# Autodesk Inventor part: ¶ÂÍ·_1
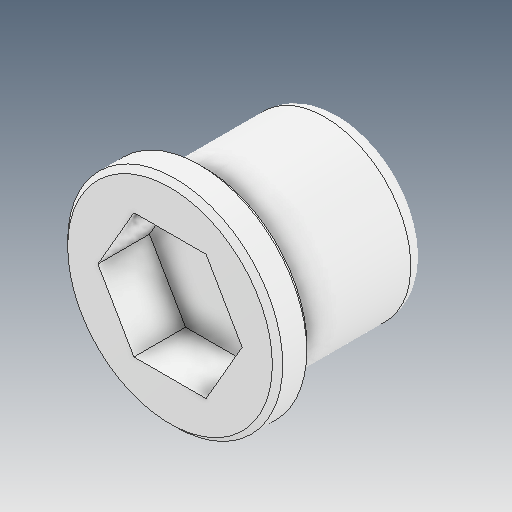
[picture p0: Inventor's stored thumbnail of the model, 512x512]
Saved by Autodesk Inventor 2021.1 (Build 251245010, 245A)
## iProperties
Created: 2021-06
Part Number: ¶ÂÍ·_1
Material: Ogólny
Document SubType Name: Modeling
Designer: user
Density: 1 g/cm^3
Appearance: Domyślna
Author: user
Revision Number: ÈÎºÎ
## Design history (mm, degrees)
feature "ÊäÈë1"
node "Bryła1"
